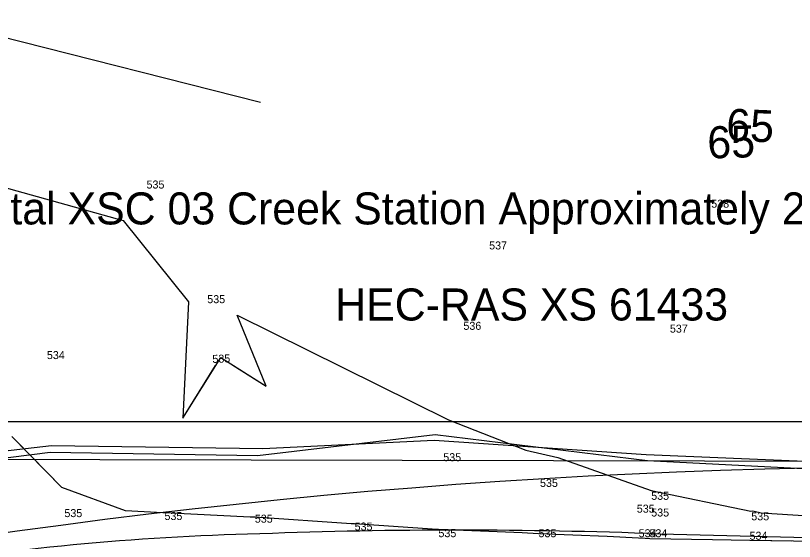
# Model space of a CAD drawing. Extents: x 1787461 to 1970323, y 938412 to 1118748.
# Drawn here: x 1967999.8 to 1968194.3, y 1117945.9 to 1118077.3 of the extents above; entities that cross this region are included whole.
import ezdxf

# ---------------------------------------------------------------- set-up
doc = ezdxf.new("R2010")
doc.units = 0
for name, color, linetype in [('Default', 7, 'Continuous'), ('HHA ADDITIONAL XSs', 7, 'Continuous'), ('Level 1', 7, 'Continuous'), ('RD_EX_Fence_Other', 7, 'Continuous'), ('RD_EX_Road', 7, 'Continuous'), ('RD_EX_VEG', 7, 'Continuous'), ('RD_HC_TX_Rel_Sta50', 7, 'Continuous'), ('RD_HC_TX_Sta50', 7, 'Continuous')]:
    doc.layers.add(name, color=color, linetype=linetype)

msp = doc.modelspace()

# ---------------------------------------------------------------- linework, layer by layer
at = {"layer": 'Default'}
for points in [[(1967915.91, 1118108.1), (1967926.19, 1118051.4), (1967926.18, 1118051.26), (1967924.01, 1118049.94), (1967926.27, 1118051.18), (1967926.72, 1118050.88), (1967992.39, 1118035.55), (1967992.88, 1118035.49), (1968026.69, 1118026.12), (1968042.97, 1118005.82), (1968041.62, 1117976.71), (1968051.06, 1117991.91), (1968062.41, 1117984.73), (1968055.12, 1118002.49), (1968107.9, 1117976.3), (1968127.27, 1117968.76), (1968135.27, 1117966.88), (1968158.58, 1117958.62), (1968183.42, 1117953.49), (1968183.93, 1117953.55), (1968186.05, 1117953.11), (1968208.47, 1117951.67)], [(1967922.52, 1118071.64), (1967926.19, 1118051.4), (1967926.18, 1118051.26), (1967924.01, 1118049.94), (1967926.27, 1118051.18), (1967926.72, 1118050.88), (1967992.39, 1118035.55), (1967992.88, 1118035.49), (1968026.69, 1118026.12), (1968042.97, 1118005.82), (1968041.62, 1117976.71), (1968049.78, 1117989.85)], [(1967922.52, 1118071.64), (1967926.19, 1118051.4), (1967926.18, 1118051.26), (1967924.01, 1118049.94), (1967926.27, 1118051.18), (1967926.72, 1118050.88), (1967992.39, 1118035.55), (1967992.88, 1118035.49), (1968026.69, 1118026.12), (1968042.97, 1118005.82), (1968041.62, 1117976.71), (1968049.78, 1117989.85)], [(1967922.52, 1118071.64), (1967926.19, 1118051.4), (1967926.18, 1118051.26), (1967924.01, 1118049.94), (1967926.27, 1118051.18), (1967926.72, 1118050.88), (1967992.39, 1118035.55), (1967992.88, 1118035.49), (1968026.69, 1118026.12), (1968042.97, 1118005.82), (1968041.62, 1117976.71), (1968049.78, 1117989.85)], [(1967922.52, 1118071.64), (1967926.19, 1118051.4), (1967926.18, 1118051.26), (1967924.01, 1118049.94), (1967926.27, 1118051.18), (1967926.72, 1118050.88), (1967992.39, 1118035.55), (1967992.88, 1118035.49), (1968026.69, 1118026.12), (1968042.97, 1118005.82), (1968041.62, 1117976.71), (1968049.78, 1117989.85)], [(1967922.52, 1118071.64), (1967926.19, 1118051.4), (1967926.18, 1118051.26), (1967924.01, 1118049.94), (1967926.27, 1118051.18), (1967926.72, 1118050.88), (1967992.39, 1118035.55), (1967992.88, 1118035.49), (1968026.69, 1118026.12), (1968042.97, 1118005.82), (1968041.62, 1117976.71), (1968049.78, 1117989.85)], [(1967922.52, 1118071.64), (1967926.19, 1118051.4), (1967926.18, 1118051.26), (1967924.01, 1118049.94), (1967926.27, 1118051.18), (1967926.72, 1118050.88), (1967992.39, 1118035.55), (1967992.88, 1118035.49), (1968026.69, 1118026.12), (1968042.97, 1118005.82), (1968041.62, 1117976.71), (1968049.78, 1117989.85)], [(1968054.07, 1117990), (1968062.41, 1117984.73), (1968055.12, 1118002.49), (1968107.9, 1117976.3), (1968127.27, 1117968.76), (1968135.27, 1117966.88), (1968158.58, 1117958.62), (1968183.42, 1117953.49), (1968183.93, 1117953.55), (1968186.05, 1117953.11), (1968208.47, 1117951.67), (1968209.08, 1117951.64), (1968212.74, 1117951.4), (1968216.23, 1117951.44)], [(1968054.07, 1117990), (1968062.41, 1117984.73), (1968055.12, 1118002.49), (1968107.9, 1117976.3), (1968127.27, 1117968.76), (1968135.27, 1117966.88), (1968158.58, 1117958.62), (1968183.42, 1117953.49), (1968183.93, 1117953.55), (1968186.05, 1117953.11), (1968208.47, 1117951.67), (1968209.08, 1117951.64), (1968212.74, 1117951.4), (1968216.23, 1117951.44)], [(1968054.07, 1117990), (1968062.41, 1117984.73), (1968055.12, 1118002.49), (1968107.9, 1117976.3), (1968127.27, 1117968.76), (1968135.27, 1117966.88), (1968158.58, 1117958.62), (1968183.42, 1117953.49), (1968183.93, 1117953.55), (1968186.05, 1117953.11), (1968208.47, 1117951.67), (1968209.08, 1117951.64), (1968212.74, 1117951.4), (1968216.23, 1117951.44)], [(1968054.07, 1117990), (1968062.41, 1117984.73), (1968055.12, 1118002.49), (1968107.9, 1117976.3), (1968127.27, 1117968.76), (1968135.27, 1117966.88), (1968158.58, 1117958.62), (1968183.42, 1117953.49), (1968183.93, 1117953.55), (1968186.05, 1117953.11), (1968208.47, 1117951.67), (1968209.08, 1117951.64), (1968212.74, 1117951.4), (1968216.23, 1117951.44)], [(1968054.07, 1117990), (1968062.41, 1117984.73), (1968055.12, 1118002.49), (1968107.9, 1117976.3), (1968127.27, 1117968.76), (1968135.27, 1117966.88), (1968158.58, 1117958.62), (1968183.42, 1117953.49), (1968183.93, 1117953.55), (1968186.05, 1117953.11), (1968208.47, 1117951.67), (1968209.08, 1117951.64), (1968212.74, 1117951.4), (1968216.23, 1117951.44)], [(1968054.07, 1117990), (1968062.41, 1117984.73), (1968055.12, 1118002.49), (1968107.9, 1117976.3), (1968127.27, 1117968.76), (1968135.27, 1117966.88), (1968158.58, 1117958.62), (1968183.42, 1117953.49), (1968183.93, 1117953.55), (1968186.05, 1117953.11), (1968208.47, 1117951.67), (1968209.08, 1117951.64), (1968212.74, 1117951.4), (1968216.23, 1117951.44)], [(1968199.55, 1117945.94), (1968183.19, 1117946.18), (1968173.9, 1117946.34), (1968158.2, 1117946.57), (1968157.07, 1117946.64), (1968155.42, 1117946.71), (1968147.53, 1117947.13), (1968130.42, 1117947.85), (1968126.34, 1117948.06), (1968105.42, 1117948.9), (1968105.07, 1117948.89), (1968084.48, 1117950.34), (1968083.59, 1117950.34), (1968059.55, 1117951.99), (1968058.39, 1117952.03), (1968037, 1117953.09), (1968036.63, 1117953.1), (1968027.25, 1117953.57), (1968011.41, 1117959.43), (1967998.86, 1117972.15)], [(1968193.68, 1117946.02), (1968183.19, 1117946.18), (1968173.9, 1117946.34), (1968158.2, 1117946.57), (1968157.07, 1117946.64), (1968155.42, 1117946.71), (1968147.53, 1117947.13), (1968130.42, 1117947.85), (1968126.34, 1117948.06), (1968105.42, 1117948.9), (1968105.07, 1117948.89), (1968084.48, 1117950.34), (1968083.59, 1117950.34), (1968059.55, 1117951.99), (1968058.39, 1117952.03), (1968037, 1117953.09), (1968036.63, 1117953.1), (1968027.25, 1117953.57), (1968011.41, 1117959.43), (1967999.84, 1117971.16)], [(1968193.68, 1117946.02), (1968183.19, 1117946.18), (1968173.9, 1117946.34), (1968158.2, 1117946.57), (1968157.07, 1117946.64), (1968155.42, 1117946.71), (1968147.53, 1117947.13), (1968130.42, 1117947.85), (1968126.34, 1117948.06), (1968105.42, 1117948.9), (1968105.07, 1117948.89), (1968084.48, 1117950.34), (1968083.59, 1117950.34), (1968059.55, 1117951.99), (1968058.39, 1117952.03), (1968037, 1117953.09), (1968036.63, 1117953.1), (1968027.25, 1117953.57), (1968011.41, 1117959.43), (1967999.84, 1117971.16)], [(1968193.68, 1117946.02), (1968183.19, 1117946.18), (1968173.9, 1117946.34), (1968158.2, 1117946.57), (1968157.07, 1117946.64), (1968155.42, 1117946.71), (1968147.53, 1117947.13), (1968130.42, 1117947.85), (1968126.34, 1117948.06), (1968105.42, 1117948.9), (1968105.07, 1117948.89), (1968084.48, 1117950.34), (1968083.59, 1117950.34), (1968059.55, 1117951.99), (1968058.39, 1117952.03), (1968037, 1117953.09), (1968036.63, 1117953.1), (1968027.25, 1117953.57), (1968011.41, 1117959.43), (1967999.84, 1117971.16)], [(1968193.68, 1117946.02), (1968183.19, 1117946.18), (1968173.9, 1117946.34), (1968158.2, 1117946.57), (1968157.07, 1117946.64), (1968155.42, 1117946.71), (1968147.53, 1117947.13), (1968130.42, 1117947.85), (1968126.34, 1117948.06), (1968105.42, 1117948.9), (1968105.07, 1117948.89), (1968084.48, 1117950.34), (1968083.59, 1117950.34), (1968059.55, 1117951.99), (1968058.39, 1117952.03), (1968037, 1117953.09), (1968036.63, 1117953.1), (1968027.25, 1117953.57), (1968011.41, 1117959.43), (1967999.84, 1117971.16)], [(1968193.68, 1117946.02), (1968183.19, 1117946.18), (1968173.9, 1117946.34), (1968158.2, 1117946.57), (1968157.07, 1117946.64), (1968155.42, 1117946.71), (1968147.53, 1117947.13), (1968130.42, 1117947.85), (1968126.34, 1117948.06), (1968105.42, 1117948.9), (1968105.07, 1117948.89), (1968084.48, 1117950.34), (1968083.59, 1117950.34), (1968059.55, 1117951.99), (1968058.39, 1117952.03), (1968037, 1117953.09), (1968036.63, 1117953.1), (1968027.25, 1117953.57), (1968011.41, 1117959.43), (1967999.84, 1117971.16)], [(1968193.68, 1117946.02), (1968183.19, 1117946.18), (1968173.9, 1117946.34), (1968158.2, 1117946.57), (1968157.07, 1117946.64), (1968155.42, 1117946.71), (1968147.53, 1117947.13), (1968130.42, 1117947.85), (1968126.34, 1117948.06), (1968105.42, 1117948.9), (1968105.07, 1117948.89), (1968084.48, 1117950.34), (1968083.59, 1117950.34), (1968059.55, 1117951.99), (1968058.39, 1117952.03), (1968037, 1117953.09), (1968036.63, 1117953.1), (1968027.25, 1117953.57), (1968011.41, 1117959.43), (1967999.84, 1117971.16)]]:
    msp.add_lwpolyline(points, dxfattribs=at)
at = {"layer": 'HHA ADDITIONAL XSs'}
msp.add_lwpolyline([(1969266.55, 1117963.61), (1967907.56, 1117966.55), (1967403.98, 1117771.66), (1967075.57, 1117641.84)], dxfattribs=at)
msp.add_arc((1968231.34, 1116297.54), 1667.02, 87.72663, 111.99584, dxfattribs=at)
at = {"layer": 'Level 1'}
msp.add_line((1968061.02, 1118055.58), (1967665.18, 1118155.96), dxfattribs=at)
msp.add_lwpolyline([(1968647.29, 1117975.82), (1967967.92, 1117975.82), (1967727.47, 1117916.63), (1966985.13, 1117603.01)], dxfattribs=at)
at = {"layer": 'RD_EX_Fence_Other'}
msp.add_lwpolyline([(1967944.7, 1118004.73), (1967946.48, 1117961.88), (1967965.46, 1117964.9), (1968008.75, 1117969.86), (1968061.54, 1117969.15), (1968104.37, 1117971.22), (1968157.32, 1117967.69), (1968212.92, 1117965.31), (1968421.1, 1117957.24), (1968536.3, 1117952.23)], dxfattribs=at)
at = {"layer": 'RD_EX_Road'}
msp.add_lwpolyline([(1968157.47, 1117947.92), (1968210.83, 1117946.57), (1968317.56, 1117942.64), (1968421.53, 1117939.29), (1968529.31, 1117935.06)], dxfattribs=at)
for centre, radius, start, end in [((1968110.17, 1116617.91), 1330.85, 87.96323, 92.25904), ((1968073.85, 1117330.01), 617.93, 91.49649, 100.12953)]:
    msp.add_arc(centre, radius, start, end, dxfattribs=at)
at = {"layer": 'RD_EX_VEG'}
msp.add_lwpolyline([(1967420.8, 1117819.08), (1967452.15, 1117758.28), (1967558.57, 1117805.53), (1967843.24, 1117926.43), (1967916.63, 1117956.61), (1968008.44, 1117968.2), (1968060.25, 1117967.44), (1968104.58, 1117972.69), (1968157.63, 1117966.15), (1968211.15, 1117963.44), (1968421.93, 1117955.99), (1968535.19, 1117951.62)], dxfattribs=at)

# ---------------------------------------------------------------- texts
at = {"layer": 'Default'}
for s, p in [('535', (1968032.52, 1118034.1)), ('538', (1968173.54, 1118029.31)), ('537', (1968118.08, 1118018.88)), ('535', (1968047.69, 1118005.46)), ('536', (1968111.65, 1117998.8)), ('537', (1968163.22, 1117998.1)), ('534', (1968007.64, 1117991.49)), ('535', (1968106.63, 1117965.98)), ('535', (1968130.79, 1117959.55)), ('535', (1968158.55, 1117956.33)), ('535', (1968154.95, 1117953.12)), ('535', (1968012.01, 1117952.01)), ('535', (1968037, 1117951.28)), ('535', (1968059.56, 1117950.62)), ('535', (1968158.56, 1117952.16)), ('535', (1968183.54, 1117951.21)), ('535', (1968084.49, 1117948.65)), ('535', (1968105.42, 1117947)), ('535', (1968130.42, 1117946.99)), ('534', (1968155.42, 1117946.98)), ('534', (1968158.12, 1117946.98)), ('534', (1968183.11, 1117946.35))]:
    msp.add_text(s, height=2, dxfattribs=at).set_placement(p)
msp.add_text('535', height=2, rotation=2.0659, dxfattribs=at).set_placement((1968049, 1117990.52))
msp.add_text('535', height=2, rotation=2.0659, dxfattribs=at).set_placement((1968049, 1117990.52))
msp.add_text('535', height=2, rotation=2.0659, dxfattribs=at).set_placement((1968049, 1117990.52))
msp.add_text('535', height=2, rotation=2.0659, dxfattribs=at).set_placement((1968049, 1117990.52))
msp.add_text('535', height=2, rotation=2.0659, dxfattribs=at).set_placement((1968049, 1117990.52))
msp.add_text('535', height=2, rotation=2.0659, dxfattribs=at).set_placement((1968049, 1117990.52))
at = {"layer": 'HHA ADDITIONAL XSs'}
for s, p in [('Supplemental XSC 03 Creek Station Approximately 25+20', (1967944.4, 1118025.13)), ('HEC-RAS XS 61433', (1968079.64, 1118001.13))]:
    msp.add_text(s, height=8, dxfattribs=at).set_placement(p)
at = {"layer": 'RD_HC_TX_Rel_Sta50'}
msp.add_text('65', height=8, rotation=1.7374, dxfattribs=at).set_placement((1968172.68, 1118041.58))
at = {"layer": 'RD_HC_TX_Sta50'}
msp.add_text('65', height=8, rotation=357.7266, dxfattribs=at).set_placement((1968177.18, 1118046.08))

doc.saveas('drawing.dxf')
